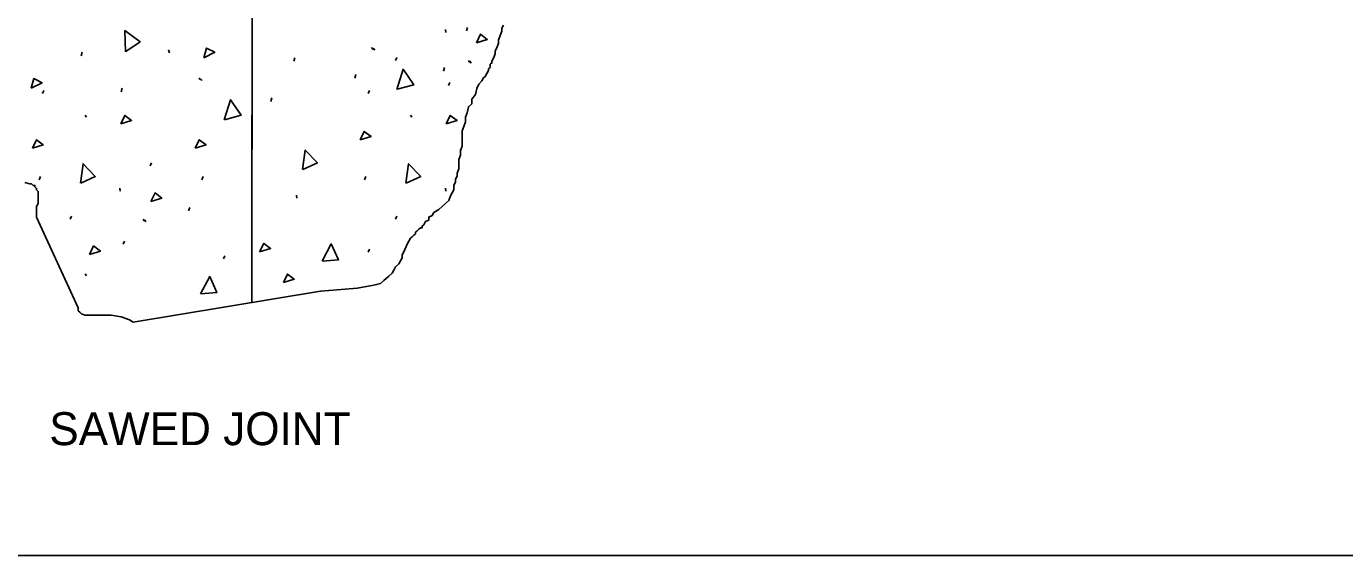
# Model space of a CAD drawing. Extents: x 49979.1 to 50021, y 49966.7 to 50011.4.
# Drawn here: x 50011.424 to 50014.623, y 49987.799 to 49989.084 of the extents above; entities that cross this region are included whole.
import ezdxf

# ---------------------------------------------------------------- set-up
doc = ezdxf.new("R2010")
doc.units = 0
for name, color, linetype in [('Level 1', 7, 'Continuous'), ('Level 13', 7, 'Continuous'), ('Level 2', 7, 'Continuous')]:
    doc.layers.add(name, color=color, linetype=linetype)

msp = doc.modelspace()

# ---------------------------------------------------------------- linework, layer by layer
at = {"layer": 'Level 1'}
msp.add_line((50011.972, 49990.2334), (50011.9714, 49988.4132), dxfattribs=at)
msp.add_lwpolyline([(49999.3835, 49998.9992), (50016.7501, 49998.9992), (50016.7501, 49987.7988), (49999.3835, 49987.7988)], close=True, dxfattribs=at)
for points in [[(50011.9714, 49988.4132), (50011.9717, 49989.3247), (50012.0446, 49989.3247)], [(50011.6837, 49988.3655), (50012.1381, 49988.4407), (50012.1381, 49988.4407), (50012.1784, 49988.4444), (50012.2269, 49988.4481), (50012.2672, 49988.4554), (50012.2834, 49988.4591), (50012.2915, 49988.4664), (50012.3036, 49988.4774), (50012.3116, 49988.4848), (50012.3157, 49988.4921), (50012.3197, 49988.4995), (50012.3278, 49988.5068), (50012.3318, 49988.5141), (50012.3359, 49988.5215), (50012.3359, 49988.5288), (50012.3399, 49988.5362), (50012.348, 49988.5545), (50012.352, 49988.5619), (50012.356, 49988.5692), (50012.3601, 49988.5729), (50012.3641, 49988.5765), (50012.3682, 49988.5802), (50012.3682, 49988.5839), (50012.3722, 49988.5876), (50012.3762, 49988.5912), (50012.3803, 49988.5949), (50012.3843, 49988.5949), (50012.3843, 49988.5986), (50012.3884, 49988.6022), (50012.3924, 49988.6096), (50012.4004, 49988.6133), (50012.4004, 49988.6206), (50012.4085, 49988.6243), (50012.4126, 49988.6316), (50012.4247, 49988.639), (50012.4328, 49988.6463), (50012.4408, 49988.6536), (50012.4489, 49988.661), (50012.4529, 49988.672), (50012.457, 49988.6793), (50012.461, 49988.6867), (50012.461, 49988.6977), (50012.465, 49988.705), (50012.465, 49988.7124), (50012.4691, 49988.7197), (50012.4691, 49988.7271), (50012.4731, 49988.7381), (50012.4731, 49988.7491), (50012.4731, 49988.7601), (50012.4772, 49988.7711), (50012.4772, 49988.7821), (50012.4812, 49988.7931), (50012.4812, 49988.8078), (50012.4812, 49988.8152), (50012.4812, 49988.8298), (50012.4852, 49988.8409), (50012.4893, 49988.8519), (50012.4893, 49988.8629), (50012.4933, 49988.8739), (50012.4973, 49988.8886), (50012.5054, 49988.8959), (50012.5054, 49988.9069), (50012.5135, 49988.9179), (50012.5175, 49988.9326), (50012.5216, 49988.9436), (50012.5296, 49988.951), (50012.5337, 49988.9583), (50012.5377, 49988.962), (50012.5417, 49988.9693), (50012.5458, 49988.9767), (50012.5458, 49988.9804), (50012.5498, 49988.984), (50012.5498, 49988.9914), (50012.5539, 49988.995), (50012.5539, 49988.9987), (50012.5579, 49989.006), (50012.5619, 49989.0171), (50012.5619, 49989.0244), (50012.5659, 49989.0317), (50012.57, 49989.0428), (50012.57, 49989.0501), (50012.5741, 49989.0611), (50012.5781, 49989.0721), (50012.5781, 49989.0795), (50012.5821, 49989.0868)], [(50011.4207, 49988.7049), (50011.4328, 49988.7012), (50011.4368, 49988.7012), (50011.4408, 49988.6976), (50011.4448, 49988.6976), (50011.4448, 49988.6939)], [(50011.4448, 49988.6939), (50011.4489, 49988.6902), (50011.4489, 49988.6866), (50011.4529, 49988.6829), (50011.4529, 49988.6792), (50011.4529, 49988.6756), (50011.4529, 49988.6719), (50011.4529, 49988.6645), (50011.4529, 49988.6609), (50011.4529, 49988.6535), (50011.4489, 49988.6462), (50011.4489, 49988.6389), (50011.4489, 49988.6316), (50011.4489, 49988.6206), (50011.5497, 49988.4006), (50011.5497, 49988.3933), (50011.5537, 49988.3896), (50011.5577, 49988.386), (50011.5658, 49988.3823), (50011.5819, 49988.3823), (50011.6303, 49988.3823), (50011.6544, 49988.3787), (50011.6746, 49988.3713), (50011.6837, 49988.3655)]]:
    msp.add_lwpolyline(points, dxfattribs=at)
at = {"layer": 'Level 13'}
for p, q in [((50012.4924, 49989.0726), (50012.4945, 49989.0811)), ((50012.4408, 49989.0757), (50012.4416, 49989.0683)), ((50011.5571, 49989.0123), (50011.5592, 49989.0207)), ((50011.7689, 49989.027), (50011.7712, 49989.0192)), ((50012.2615, 49989.0319), (50012.266, 49989.0272)), ((50012.2654, 49989.0305), (50012.2698, 49989.0259)), ((50012.0735, 49988.9987), (50012.0756, 49989.0072)), ((50012.3199, 49989.0008), (50012.3232, 49989.0082)), ((50012.4366, 49988.9751), (50012.4387, 49988.9836)), ((50012.4971, 49989.0008), (50012.5004, 49988.9959)), ((50012.5004, 49988.9989), (50012.5037, 49988.994)), ((50011.8426, 49988.958), (50011.8471, 49988.9534)), ((50011.8465, 49988.9566), (50011.8509, 49988.952)), ((50012.2214, 49988.9579), (50012.2235, 49988.9664)), ((50011.4634, 49988.9207), (50011.4667, 49988.9282)), ((50011.6546, 49988.9248), (50011.6567, 49988.9333)), ((50012.2531, 49988.9207), (50012.2564, 49988.9282)), ((50012.4485, 49988.9397), (50012.4518, 49988.9471)), ((50012.0177, 49988.9013), (50012.0198, 49988.9098)), ((50011.5665, 49988.868), (50011.5698, 49988.863)), ((50012.3561, 49988.868), (50012.3594, 49988.863)), ((50011.7247, 49988.7452), (50011.7281, 49988.7526)), ((50011.4552, 49988.7114), (50011.4585, 49988.7188)), ((50011.85, 49988.7114), (50011.8533, 49988.7188)), ((50012.2449, 49988.7114), (50012.2481, 49988.7188)), ((50011.6512, 49988.6907), (50011.652, 49988.6833)), ((50012.0793, 49988.674), (50012.0801, 49988.6666)), ((50012.4408, 49988.6907), (50012.4416, 49988.6833)), ((50011.8179, 49988.6361), (50011.8212, 49988.6435)), ((50011.5302, 49988.6158), (50011.5335, 49988.6232)), ((50011.7074, 49988.6158), (50011.7107, 49988.6108)), ((50011.7107, 49988.6139), (50011.714, 49988.6089)), ((50012.3199, 49988.6158), (50012.3232, 49988.6232)), ((50011.6588, 49988.5547), (50011.6621, 49988.5621)), ((50012.2531, 49988.5357), (50012.2564, 49988.5431)), ((50011.9026, 49988.5191), (50011.9059, 49988.5265)), ((50011.5665, 49988.483), (50011.5698, 49988.478))]:
    msp.add_line(p, q, dxfattribs=at)
for points in [[(50011.6651, 49989.022), (50011.6632, 49989.0732), (50011.7003, 49989.0464), (50011.6659, 49989.0224)], [(50012.5161, 49989.0436), (50012.5259, 49989.0643), (50012.5424, 49989.0519), (50012.5161, 49989.0436)], [(50011.8547, 49989.007), (50011.8614, 49989.0307), (50011.8812, 49989.0207), (50011.8547, 49989.007)], [(50011.4358, 49988.9332), (50011.4425, 49988.9569), (50011.4623, 49988.9468), (50011.4358, 49988.9332)], [(50012.3227, 49988.9307), (50012.3384, 49988.9795), (50012.364, 49988.9416), (50012.3236, 49988.9309)], [(50011.9038, 49988.8569), (50011.9195, 49988.9056), (50011.9451, 49988.8678), (50011.9046, 49988.857)], [(50011.653, 49988.8466), (50011.6629, 49988.8672), (50011.6794, 49988.8548), (50011.653, 49988.8466)], [(50012.4427, 49988.8466), (50012.4526, 49988.8672), (50012.4691, 49988.8548), (50012.4427, 49988.8466)], [(50012.2341, 49988.808), (50012.244, 49988.8286), (50012.2605, 49988.8162), (50012.2341, 49988.808)], [(50011.4389, 49988.7876), (50011.4488, 49988.8082), (50011.4652, 49988.7959), (50011.4389, 49988.7876)], [(50011.8337, 49988.7876), (50011.8436, 49988.8082), (50011.8601, 49988.7959), (50011.8337, 49988.7876)], [(50012.0944, 49988.7361), (50012.1009, 49988.7832), (50012.1304, 49988.7527), (50012.0952, 49988.7364)], [(50011.5555, 49988.7029), (50011.562, 49988.75), (50011.5915, 49988.7195), (50011.5562, 49988.7031)], [(50012.3451, 49988.7029), (50012.3517, 49988.75), (50012.3812, 49988.7195), (50012.3459, 49988.7031)], [(50011.7264, 49988.6586), (50011.7363, 49988.6792), (50011.7528, 49988.6669), (50011.7264, 49988.6586)], [(50011.5773, 49988.5299), (50011.5872, 49988.5505), (50011.6037, 49988.5381), (50011.5773, 49988.5299)], [(50011.9902, 49988.5363), (50012.0001, 49988.5569), (50012.0166, 49988.5446), (50011.9902, 49988.5363)], [(50012.1418, 49988.5135), (50012.1641, 49988.5555), (50012.1814, 49988.5168), (50012.1427, 49988.5135)], [(50011.8468, 49988.434), (50011.869, 49988.476), (50011.8863, 49988.4373), (50011.8476, 49988.434)], [(50012.0479, 49988.4615), (50012.0577, 49988.4821), (50012.0742, 49988.4698), (50012.0479, 49988.4615)]]:
    msp.add_lwpolyline(points, dxfattribs=at)

# ---------------------------------------------------------------- texts
at = {"layer": 'Level 2'}
msp.add_text('SAWED JOINT', height=0.08, dxfattribs=at).set_placement((50011.4798, 49988.067))

doc.saveas('drawing.dxf')
